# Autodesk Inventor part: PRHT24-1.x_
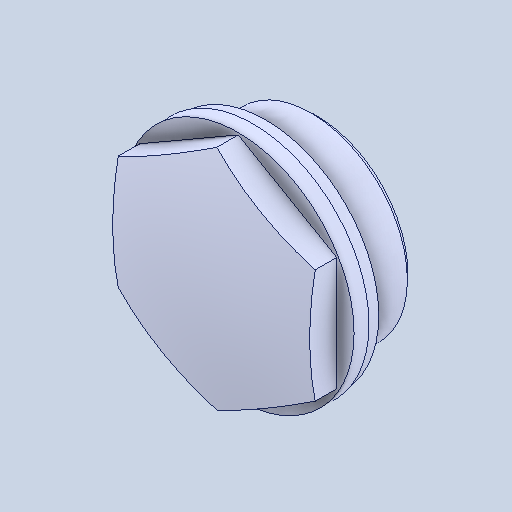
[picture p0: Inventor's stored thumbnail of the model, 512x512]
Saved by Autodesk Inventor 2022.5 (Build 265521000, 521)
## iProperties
Created: 2024-05
Part Number: PRHT24-1.x_
Material: 一般
Document SubType Name: Modeling
Designer: ImaoCorp
Density: 1 g/cm^3
Appearance: 既定
Author: ImaoCorp
Sending System: SOLIDWORKS 2022-2022290
MC: AMD64
MC_MODEL: Intel64 Family 6 Model 60 Stepping 3, GenuineIntel
OS: Windows_NT
FRU: Parasolid Version 33.1, build 260,  4-25-2022
FORMAT: text
GUISE: transmit
KEY: FILEPRHT24-1.x_t
DATE: Mon May 20 16:41:21 2024
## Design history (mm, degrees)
feature "Base1"
node "ソリッド1"
